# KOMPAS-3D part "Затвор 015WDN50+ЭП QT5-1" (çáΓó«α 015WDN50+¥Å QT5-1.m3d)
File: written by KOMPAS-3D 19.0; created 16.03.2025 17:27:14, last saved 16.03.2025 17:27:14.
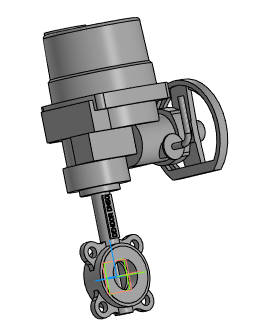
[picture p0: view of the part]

Document properties: Полное имя файла: Затвор 015WDN50+ЭП QT5-1.a3d

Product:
- Part/product: Затвор 015WDN50+ЭП QT5-1
    Масса: 43.1317

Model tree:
1. Операция без истории:1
